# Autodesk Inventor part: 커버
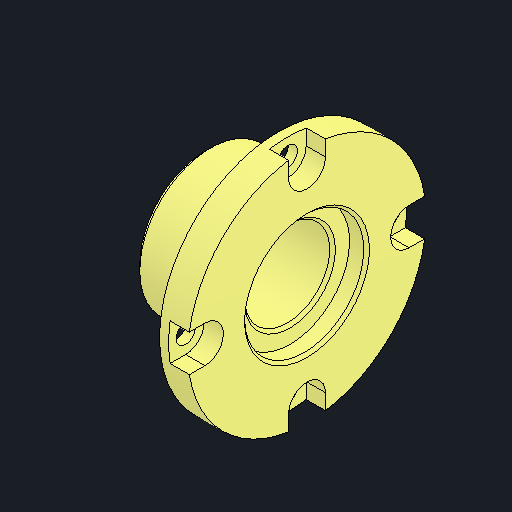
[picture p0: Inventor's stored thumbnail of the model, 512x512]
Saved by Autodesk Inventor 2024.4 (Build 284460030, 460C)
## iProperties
Created: 2026-08
Part Number: 커버
Material: 알루미늄 6061
Document SubType Name: Modeling
Designer: user
Density: 2.71 g/cm^3
Appearance: 기본값
Author: jhkim
Sending System: Autodesk Inventor 2027
Preprocessor: ST-DEVELOPER v20.1
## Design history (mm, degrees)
feature "솔리드1"
node "솔리드2"
